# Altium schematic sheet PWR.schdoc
size 420 x 297 mm; Symbol: Drawing-Symbol_A4; Company: 嘉立创EDA; Version: V1.0; Page Size: A4; @Project Name: mairui N1; @Update Date: 2026-05-09; @Create Date: 2026-05-09; Device: Drawing-Symbol_A4; @Board Name: 顶板_2; @Page Name: P2; @Create Time: 15:52:06; @Page Count: 4; @Page No: 4; @Schematic Name: Top_2; @Update Time: 15:52:06; @Assembly Variant: Basic; Border: 1; Title Block Position: 3; Size: A4; Width: 1655; Height: 1170; Region Start: 1; X Region Count: 6; Y Region Count: 4; Blade Width: 10
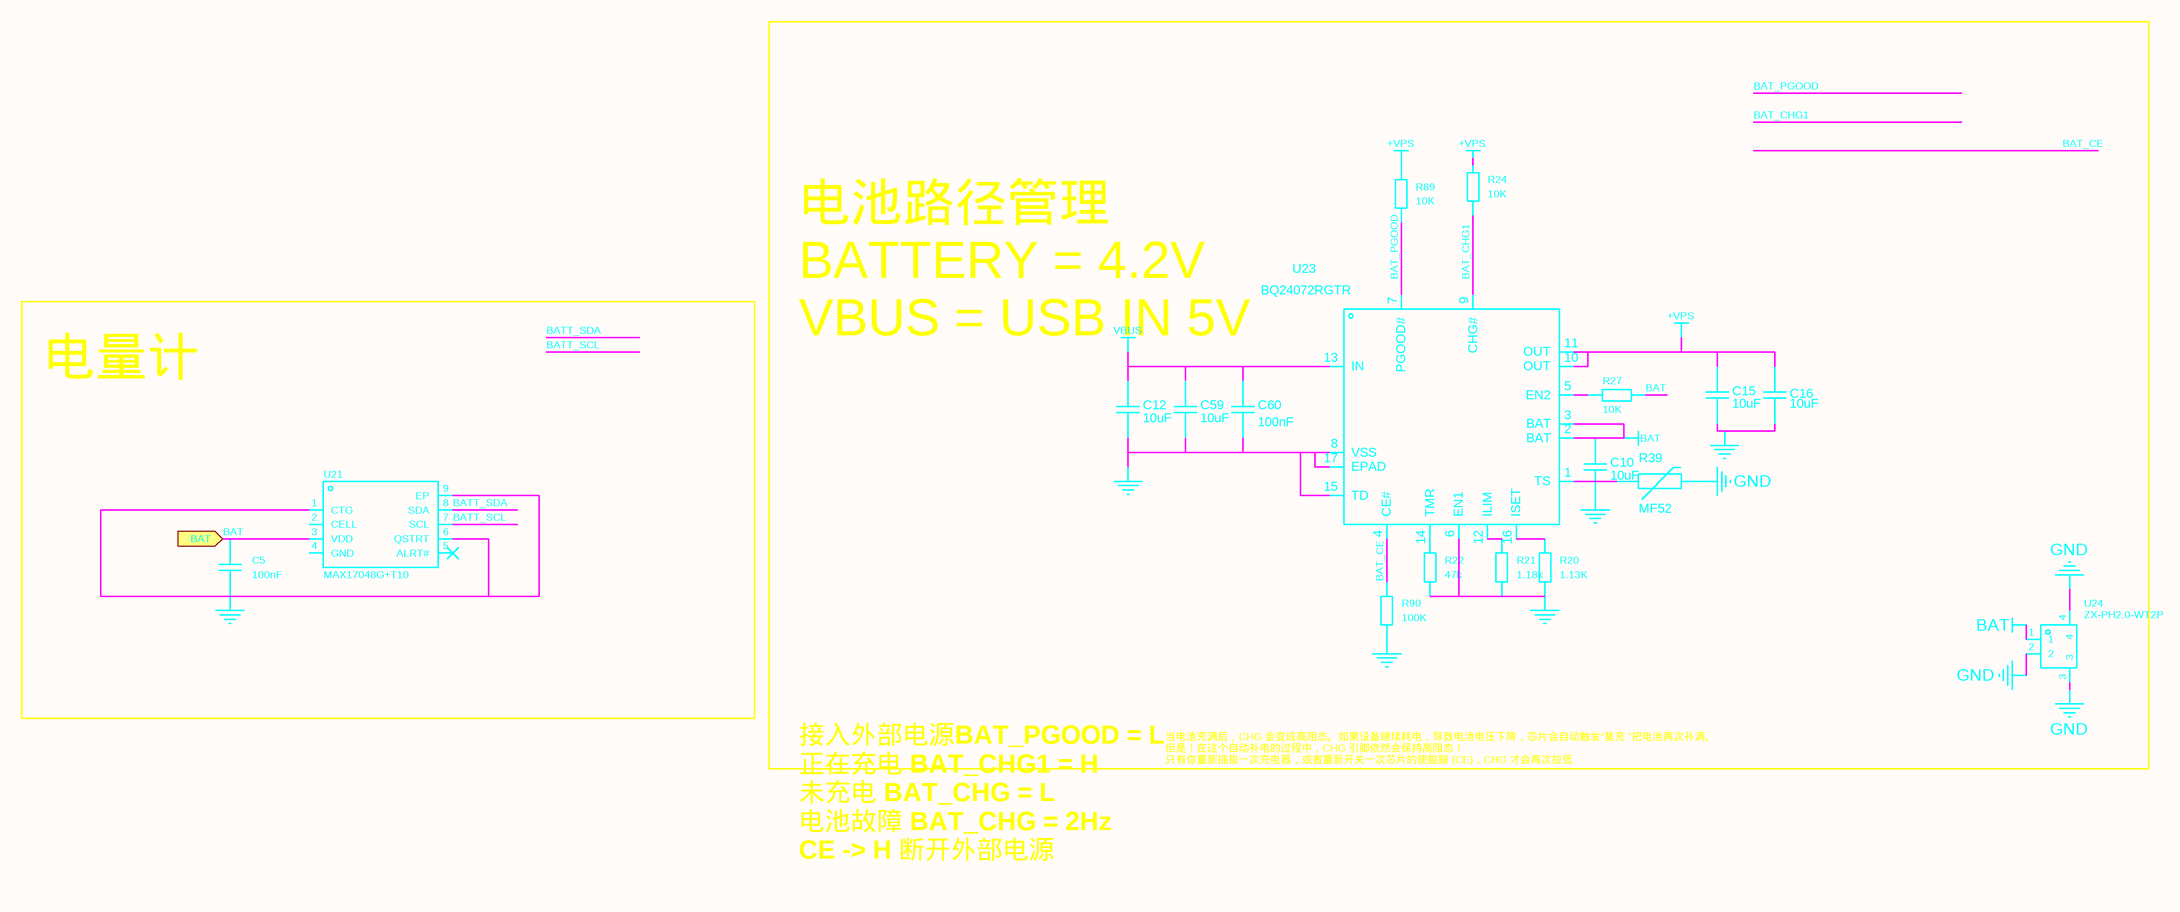
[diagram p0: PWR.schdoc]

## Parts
C5  100nF  [C0603]
C10  10uF  [C0603]
C12  10uF  [C0805]
C15  10uF  [C0805]
C16  10uF  [C0805]
C59  10uF  [C0805]
C60  100nF  [C0603]
R20  1.13K  [R0603]
R21  1.18k  [R0603]
R22  47k  [R0603]
R24  10K  [R0603]
R27  10K  [R0603]
R39  MF52  [R0603]
R89  10K  [R0603]
R90  100K  [R0603]
U21  MAX17048G+T10  [TDFN-8_L2.0-W2.0-P0.50-BL-EP1.2]
U23  BQ24072RGTR  [QFN-16_L3.0-W3.0-P0.50-TL-EP]
U24  ZX-PH2.0-WT2P  [CONN-SMD_ZX-PH2.0-WT2P]

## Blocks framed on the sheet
电量计: C5 U21

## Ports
BAT (in)

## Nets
+VPS: C15.2 C16.2 R24.2 R89.2 U23.10(OUT) U23.11(OUT)
BAT: C5.2 C10.2 R27.1 U21.3(VDD) U23.2(BAT) U23.3(BAT) U24.1 ; port BAT
GND: C5.1 C10.1 C12.1 C15.1 C16.1 C59.1 C60.1 R20.1 R21.1 R22.1 R39.1 R90.1 U21.1(CTG) U21.6(QSTRT) U21.9(EP) U23.6(EN1) U23.8(VSS) U23.15(TD) U23.17(EPAD) U24.2 U24.3 U24.4
VBUS: C12.2 C59.2 C60.2 U23.13(IN)
BAT_CE: R90.2 U23.4(CE#)
BAT_CHG1: R24.1 U23.9(CHG#)
BAT_PGOOD: R89.1 U23.7(PGOOD#)
BATT_SCL: U21.7(SCL)
BATT_SDA: U21.8(SDA)
NetR20_2: R20.2 U23.16(ISET)
NetR21_2: R21.2 U23.12(ILIM)
NetR22_2: R22.2 U23.14(TMR)
NetR27_2: R27.2 U23.5(EN2)
NetR39_2: R39.2 U23.1(TS)

Not connected (* = marked no-connect by the designer): U21 2(CELL) 4(GND) 5(ALRT#)*

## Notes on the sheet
- 电池路径管理
  BATTERY = 4.2V
  VBUS = USB IN 5V
- 接入外部电源BAT_PGOOD = L
  正在充电 BAT_CHG1 = H
  未充电 BAT_CHG = L
  电池故障 BAT_CHG = 2Hz
  CE -> H 断开外部电源
- 当电池充满后，CHG 会变成高阻态。如果设备继续耗电，导致电池电压下降，芯片会自动触发“复充 ”把电池再次补满。
  但是！在这个自动补电的过程中，CHG 引脚依然会保持高阻态！
  只有你重新插拔一次充电器，或者重新开关一次芯片的使能脚 (CE)，CHG 才会再次拉低

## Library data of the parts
C5 = CAP_0603: Symbol: Capacitance; 3D Model: ac125912035d415993ca9572d50418b1; 3D Model Transform: 62.992,31.496,0,0,0,0,0,0,0; ConvertToPcb: yes; ModelName: C0603_L1.6-W0.8-H0.8
C10 C12 C15 C16 C59 = CL10A106KP8NNNC: Manufacturer: SAMSUNG; Add into BOM: yes; Origin 3D Model Title: C0603_L1.6-W0.8-H0.8
C60 = CC0603KRX7R9BB104: Manufacturer: YAGEO; Add into BOM: yes; Origin 3D Model Title: C0603_L1.6-W0.8-H0.8
R20-R22 R24 R27 R89 R90 = Res_0603: Symbol: 电阻; 3D Model: fc143cca1e79419f9cd78b61e9279f08; 3D Model Transform: 31.8897,63.7794,0,90,0,0,0,0,0; ConvertToPcb: yes
R39 = MF52: Manufacturer: Shiheng; Manufacturer Part: MF52A1104F3950(P209-15A); Add into BOM: yes; Origin 3D Model Title: RES-TH_L2.5-W2.5-P1.70
U21 = MAX17048G+T10: 工作电压:2.5V~4.5V;最大充电电流:-;电池类型:锂电池;电池节数:1;; Manufacturer: ADI(亚德诺)/MAXIM(美信); 3D Model: 8ccff341f378482fb835cd62a8fe8c670819f05c4eef4c71ace90d822a990e87; 3D Model Transform: 78.74,79.527,0,0,0,0,0,0,0; The Chip Type: 监测芯片; Type of Battery: 锂电池; Number of Cells: 1; Battery Temperature Detection: 不支持; Supply Current (Iq): 3uA; Interface: I2C; AddInBom: yes
U23 = BQ24072RGTR: Manufacturer: Texas Instruments; Add into BOM: yes; Origin 3D Model Title: QFN-16_L3.0-W3.0-H0.9-P0.50
U24 = ZX-PH2.0-WT2P: 插针结构:1x2P;间距:2mm;安装方式:卧贴;参考系列:PH;总PIN数:2P;排数:1;每排PIN数:2;行距:-;额定电流:2A;触头材质:黄铜;触头镀层:锡;工作温度:-25℃~+85℃;; Manufacturer: Megastar(兆星); AddInBom: yes; ModelId: 06be73072cd946eca23225be08c59a5b0819f05c4eef4c71ace90d822a990e87; ModelTransform: 314.96,334.645,0,0,0,0,-0.001,-9.406,0; Pins Structure: 1x2P; Pitch: 2mm; Reference Series: PH; Number of PINs Per Row: 2; Current Rating: 2A; Voltage Rating: 250V; Plastic Material: LCP; Supplementary Features: 辅助焊脚; Z-Height of the Board: 5.6mm; X-Length of Bottom Edge on Board (Spacing Line): 8mm; Y-Width of Bottom Edge on Board: 7.59mm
